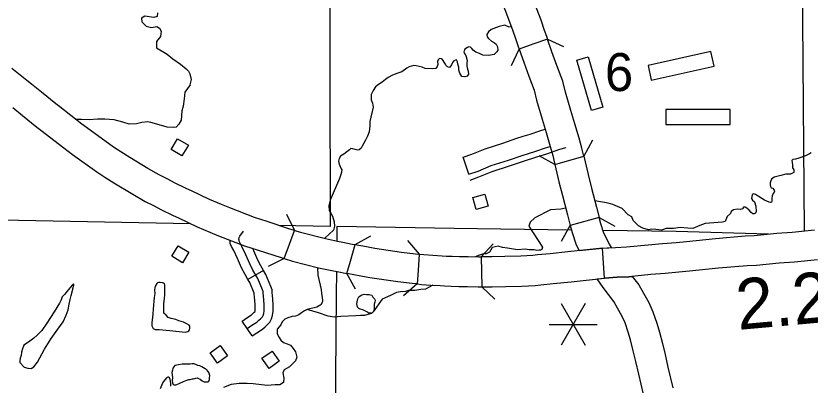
# Model space of a CAD drawing. Extents: x 61396 to 64680, y 55472 to 57605.
# Drawn here: x 62536.1 to 62743.1, y 56330.1 to 56426.3 of the extents above; entities that cross this region are included whole.
import ezdxf

# ---------------------------------------------------------------- set-up
doc = ezdxf.new("R2010")
doc.units = 0
for name, color, linetype in [('15', 7, 'Continuous'), ('32', 7, 'Continuous'), ('35', 7, 'Continuous'), ('37', 7, 'Continuous'), ('4', 7, 'Continuous'), ('45', 7, 'Continuous'), ('48', 7, 'Continuous'), ('5', 7, 'Continuous'), ('56', 7, 'Continuous'), ('57', 7, 'Continuous'), ('6', 7, 'Continuous')]:
    doc.layers.add(name, color=color, linetype=linetype)

msp = doc.modelspace()

# ---------------------------------------------------------------- linework, layer by layer
at = {"layer": '15'}
for p, q in [((62676.6, 56387.58), (62684.11, 56389.78)), ((62688.12, 56373.73), (62680.58, 56371.68))]:
    msp.add_line(p, q, dxfattribs=at)
for points in [[(62668.98, 56435.84), (62669.25, 56435.05), (62670.84, 56430.76), (62672.94, 56425.31), (62673.78, 56422.64), (62674.37, 56421), (62674.64, 56420.26)], [(62661.67, 56433.08), (62661.89, 56432.43), (62663.53, 56428), (62665.56, 56422.73), (62666.38, 56420.14), (62667.02, 56418.37), (62667.27, 56417.66)], [(62674.64, 56420.26), (62670.82, 56418.91), (62667.27, 56417.66), (62668.46, 56414.29), (62669.78, 56410.65), (62671.16, 56406.96), (62671.83, 56404.38), (62673.26, 56399.42), (62674.32, 56395.96), (62675.38, 56392.29), (62676.04, 56389.89), (62676.52, 56387.94), (62676.6, 56387.58)], [(62684.11, 56389.78), (62683.6, 56391.87), (62682.89, 56394.41), (62681.81, 56398.18), (62680.75, 56401.64), (62679.37, 56406.44), (62678.62, 56409.32), (62677.11, 56413.35), (62675.82, 56416.92), (62674.64, 56420.26)], [(62608.67, 56370.42), (62607.53, 56370.76), (62601.62, 56372.71), (62598.29, 56373.8), (62591.81, 56376.25), (62589.69, 56377.15), (62586.56, 56378.46), (62581.82, 56380.7), (62580.47, 56381.34), (62577.46, 56382.82), (62575.72, 56383.78), (62573.41, 56384.91), (62570.48, 56386.55), (62565.79, 56389.39), (62563.47, 56390.89), (62561.55, 56392.13), (62555.47, 56396.5), (62553.28, 56398.14), (62547.49, 56402.6), (62546.5, 56403.41), (62542.75, 56406.41), (62540.14, 56408.54), (62538.95, 56409.48), (62535.04, 56412.59)], [(62535.24, 56402.45), (62537.84, 56400.33), (62541.57, 56397.35), (62542.62, 56396.49), (62548.56, 56391.91), (62550.85, 56390.2), (62557.16, 56385.66), (62559.24, 56384.32), (62561.65, 56382.77), (62566.54, 56379.81), (62569.78, 56377.98), (62572.13, 56376.84), (62573.86, 56375.89), (62577.07, 56374.31), (62578.47, 56373.64), (62583.37, 56371.33), (62586.65, 56369.95), (62588.9, 56369), (62595.7, 56366.42), (62599.19, 56365.29), (62605.19, 56363.3), (62606.02, 56363.06), (62607.38, 56366.84), (62608.67, 56370.42)], [(62684.11, 56389.78), (62684.12, 56389.75), (62685.23, 56384.94), (62686.14, 56381.4), (62687.4, 56376.46), (62688.12, 56373.73)], [(62676.6, 56387.58), (62677.64, 56383.08), (62678.58, 56379.46), (62679.83, 56374.5), (62680.58, 56371.68)], [(62691.35, 56365.93), (62690.83, 56366.78), (62689.36, 56369.68), (62688.55, 56372.12), (62688.12, 56373.73)], [(62680.58, 56371.68), (62681.06, 56369.87), (62682.14, 56366.67), (62682.91, 56365.13)], [(62608.67, 56370.42), (62610.23, 56369.96), (62616.8, 56368.29), (62619.94, 56367.6), (62621.33, 56367.37), (62623.78, 56366.85), (62624.51, 56366.72)], [(62689.5, 56357.98), (62689, 56365.78), (62692.37, 56365.99), (62695.29, 56366.13), (62700.87, 56366.66), (62704.65, 56366.98), (62708.19, 56367.26), (62710.89, 56367.54), (62718.47, 56368.33), (62726.21, 56368.97), (62728.56, 56369.09), (62734.42, 56369.67), (62738.41, 56369.93), (62744.28, 56370.54)], [(62640.69, 56356.44), (62639.4, 56356.56), (62635.62, 56357.02), (62628.36, 56358.03), (62626.03, 56358.49), (62622.35, 56359.17), (62623.26, 56362.38), (62624.51, 56366.72)], [(62624.51, 56366.72), (62627.5, 56366.17), (62629.66, 56365.74), (62636.63, 56364.77), (62640.22, 56364.33), (62641.24, 56364.24), (62640.94, 56359.91), (62640.69, 56356.44)], [(62689.5, 56357.98), (62689, 56365.78), (62679.97, 56364.81), (62675.38, 56364.33), (62672.08, 56364), (62670.8, 56363.86), (62667.7, 56363.72), (62663.55, 56363.6), (62660.16, 56363.52), (62657.99, 56363.52), (62657.33, 56363.53), (62657.43, 56359.6), (62657.53, 56355.71)], [(62682.91, 56365.13), (62689, 56365.78), (62691.35, 56365.93)], [(62606.02, 56363.06), (62608.17, 56362.42), (62615, 56360.68), (62618.45, 56359.93), (62619.87, 56359.69), (62622.35, 56359.17)], [(62641.24, 56364.24), (62642.44, 56364.13), (62644.74, 56363.95), (62647.2, 56363.81), (62648.29, 56363.72), (62649.78, 56363.66), (62651.68, 56363.63), (62653.94, 56363.57), (62656.72, 56363.54), (62657.33, 56363.53)], [(62745.06, 56362.77), (62739.07, 56362.15), (62735.07, 56361.88), (62729.14, 56361.29), (62726.73, 56361.17), (62719.2, 56360.55), (62711.69, 56359.76), (62708.89, 56359.48), (62705.3, 56359.2), (62701.58, 56358.88), (62695.84, 56358.33), (62692.8, 56358.19), (62689.5, 56357.98)], [(62657.53, 56355.71), (62657.89, 56355.7), (62660.26, 56355.7), (62663.76, 56355.79), (62667.99, 56355.91), (62671.41, 56356.07), (62672.89, 56356.23), (62676.17, 56356.56), (62680.79, 56357.04), (62689.5, 56357.98)], [(62687.63, 56357.78), (62689.5, 56357.98), (62692.8, 56358.19), (62695.84, 56358.33), (62696.77, 56358.42)], [(62699.69, 56327.72), (62698.46, 56332.97), (62697.69, 56336.25), (62697.03, 56339), (62696.27, 56341.86), (62695.71, 56343.9), (62694.87, 56346.3), (62694.06, 56348.15), (62692.91, 56350.17), (62691.92, 56351.88), (62689.17, 56355.5), (62687.63, 56357.78)], [(62696.77, 56358.42), (62698.44, 56356.22), (62699.7, 56354.06), (62701.06, 56351.64), (62702.14, 56349.17), (62703.17, 56346.24), (62703.82, 56343.89), (62704.6, 56340.92), (62705.29, 56338.06), (62706.06, 56334.76), (62707.32, 56329.4)], [(62640.69, 56356.44), (62641.79, 56356.34), (62644.21, 56356.16), (62646.66, 56356.01), (62647.84, 56355.92), (62649.58, 56355.85), (62651.52, 56355.82), (62653.8, 56355.76), (62656.59, 56355.73), (62657.53, 56355.71)]]:
    msp.add_lwpolyline(points, dxfattribs=at)
at = {"layer": '32'}
for p, q in [((62600.61, 56359.98), (62596.56, 56357.63)), ((62597.66, 56342.89), (62595.05, 56346.78))]:
    msp.add_line(p, q, dxfattribs=at)
for points in [[(62596.35, 56344.83), (62597.58, 56345.66), (62598.91, 56346.5), (62599.44, 56346.99), (62599.84, 56347.37), (62600.35, 56347.88), (62600.55, 56348.26), (62600.71, 56348.74), (62600.8, 56349.43), (62600.77, 56350.01), (62600.8, 56350.92), (62600.73, 56352.36), (62600.64, 56353.16), (62600.57, 56354.12), (62600.57, 56354.45), (62600.4, 56354.9), (62599.13, 56357.87), (62597.86, 56360.05), (62597.04, 56361.65), (62595.98, 56364.07), (62594.94, 56366.22), (62594.42, 56367.21), (62594.26, 56367.56), (62594.24, 56367.85), (62594.23, 56368.12), (62594.31, 56368.59), (62594.44, 56368.89), (62595.45, 56370.2)], [(62596.56, 56357.63), (62595.81, 56358.92), (62594.93, 56360.64), (62593.85, 56363.09), (62592.85, 56365.17), (62592.31, 56366.18), (62591.96, 56366.97), (62591.9, 56367.71), (62591.9, 56367.86)], [(62600.61, 56359.98), (62599.92, 56361.18), (62599.16, 56362.66), (62598.11, 56365.05), (62597.77, 56365.75)], [(62597.66, 56342.89), (62598.86, 56343.69), (62600.34, 56344.63), (62601.04, 56345.27), (62601.47, 56345.69), (62602.26, 56346.47), (62602.72, 56347.34), (62603, 56348.23), (62603.15, 56349.33), (62603.12, 56350.03), (62603.14, 56350.95), (62603.07, 56352.55), (62602.98, 56353.38), (62602.92, 56354.2), (62602.92, 56354.9), (62602.56, 56355.79), (62601.23, 56358.93), (62600.61, 56359.98)], [(62595.05, 56346.78), (62596.29, 56347.62), (62597.48, 56348.37), (62597.84, 56348.71), (62598.21, 56349.05), (62598.41, 56349.25), (62598.41, 56349.25), (62598.45, 56349.54), (62598.43, 56349.99), (62598.45, 56350.9), (62598.39, 56352.18), (62598.31, 56352.95), (62598.23, 56353.99), (62598.23, 56354), (62597.03, 56356.82), (62596.56, 56357.63)]]:
    msp.add_lwpolyline(points, dxfattribs=at)
at = {"layer": '35'}
for points in [[(62573.02, 56427.09), (62572.87, 56426.19), (62572.02, 56425.89), (62569.68, 56426.29), (62568.84, 56425.69), (62568.89, 56424.75), (62570.08, 56423.65), (62571.47, 56423.31), (62572.82, 56423.55), (62573.51, 56423.11), (62573.96, 56422.36), (62573.76, 56420.92), (62572.77, 56419.67), (62572.77, 56418.03), (62575.54, 56416.32), (62577.01, 56415.11), (62578.97, 56413.76), (62580.48, 56412.49), (62581.09, 56411.88), (62581.46, 56411.2), (62581.81, 56409.74), (62581.45, 56408.38), (62581.51, 56408.32), (62580.1, 56406.42), (62579.9, 56404.69), (62579.64, 56402.83), (62579.34, 56401.59), (62579.28, 56400.3), (62579.13, 56399.14), (62578.54, 56398.12), (62577.84, 56397.34), (62577.06, 56397.19), (62575.49, 56397.3), (62573.4, 56397.92), (62571.29, 56398.54), (62570.37, 56398.67), (62568.88, 56398.5), (62567.54, 56398.2), (62565.63, 56398.14), (62563.95, 56398.65), (62561.68, 56399.24), (62559.27, 56399.38)], [(62665.25, 56423.55), (62664.69, 56423.35), (62663.5, 56423.88), (62662.08, 56423.59), (62659.97, 56422.81), (62659.27, 56422.19), (62658.88, 56421.49), (62658.93, 56420.89), (62659.32, 56420.43), (62660.03, 56419.76), (62660.8, 56419.29), (62661.25, 56418.92), (62661.64, 56418.28), (62661.73, 56417.37), (62661.46, 56416.95), (62660.73, 56416.27), (62659.27, 56416.01), (62657.83, 56416.05), (62656.9, 56416.5), (62655.98, 56416.87), (62655.25, 56417.38), (62654.95, 56417.78), (62654.57, 56418.15), (62654.19, 56418.26), (62653.79, 56418.09), (62653.08, 56417.69), (62652.88, 56416.96), (62653.12, 56416.34), (62653.38, 56415.97), (62653.7, 56414.73), (62653.66, 56413.88), (62653.59, 56413.19), (62653.77, 56412.44), (62653.94, 56411.91), (62654.03, 56411.1), (62653.7, 56410.62), (62653.08, 56410.41), (62652.36, 56410.54), (62651.83, 56411.37), (62651.58, 56412.21), (62651.53, 56412.93), (62651.32, 56413.74), (62651.17, 56414.37), (62651.04, 56414.71), (62650.94, 56414.83), (62650.69, 56414.79), (62650.23, 56414.62), (62649.9, 56414.17), (62649.63, 56413.6), (62649.24, 56412.99), (62648.93, 56412.91), (62648.33, 56413.21), (62648.06, 56413.7)], [(62648.06, 56413.7), (62647.76, 56414.29), (62647.5, 56414.72), (62647.24, 56415.06), (62647.05, 56415.15), (62646.48, 56415.25), (62646.15, 56414.83), (62645.97, 56414.42), (62646.03, 56413.64), (62645.89, 56413.13), (62645.53, 56412.65), (62644.75, 56412.5), (62642.8, 56412.59), (62641.98, 56412.97), (62640.4, 56413.3), (62639.8, 56413.38), (62638.56, 56413.02), (62638.01, 56412.66), (62636.69, 56411.74), (62635.36, 56411.29), (62634.21, 56410.84), (62633.1, 56410.28), (62632.43, 56409.72), (62631.54, 56409.03), (62630.59, 56408.41), (62629.83, 56407.82), (62629.2, 56406.89), (62628.73, 56405.8), (62628.71, 56404.45), (62629.05, 56403.59), (62629.2, 56402.52), (62628.32, 56398.76), (62628.38, 56397.67), (62628.18, 56396.12), (62627.74, 56394.98), (62627.21, 56393.89), (62626.77, 56393.16), (62626.32, 56392.33), (62626.09, 56391.85), (62625.53, 56391.42), (62625.19, 56391.35), (62624.53, 56391.45), (62623.93, 56391.69), (62623.4, 56391.73), (62623, 56391.44), (62622.39, 56390.92), (62621.56, 56390.29), (62620.73, 56389.76), (62620.34, 56389.19), (62620.18, 56388.43), (62620.39, 56387.68), (62620.83, 56386.47), (62621.03, 56386.16), (62620.9, 56385.28), (62620.47, 56383.92), (62618.04, 56378.25), (62617.62, 56376.89), (62617.72, 56375.61), (62618.25, 56374.75), (62618.61, 56374.1), (62619.06, 56372.67), (62619.1, 56371.51), (62618.88, 56370.5), (62616.57, 56368.35)], [(62559.27, 56399.38), (62557.38, 56399.42), (62555.14, 56399.22), (62553.19, 56399.31), (62551.83, 56399.33)], [(62743.43, 56390.66), (62742.92, 56390.33), (62741.9, 56389.85), (62740.21, 56389.2), (62739.28, 56389.01), (62738.64, 56388.92), (62738.31, 56388.6), (62738.4, 56388.13), (62738.54, 56387.53), (62738.52, 56386.68), (62738.87, 56386.17), (62738.91, 56385.82), (62738.87, 56385.52), (62738.54, 56385.29), (62737.99, 56385.08), (62736.81, 56385.03), (62735.46, 56384.71), (62733.72, 56384.29), (62733.08, 56383.8), (62732.89, 56383.36), (62732.73, 56382.81), (62732.68, 56382.25), (62732.75, 56381.86), (62732.94, 56381.53), (62733.38, 56381.4), (62733.72, 56380.93), (62733.82, 56380.65), (62733.75, 56380.35), (62733.52, 56380.01), (62733.26, 56379.4), (62733.15, 56378.76), (62733.15, 56378.22), (62733.15, 56377.94), (62733.03, 56377.74), (62732.75, 56377.64), (62732.45, 56377.76), (62731.25, 56378.27), (62728.84, 56379.8), (62728.37, 56379.96), (62728, 56379.73), (62727.89, 56379.15), (62727.86, 56378.71), (62728.12, 56378.32), (62728.61, 56377.81), (62728.95, 56376.76), (62729.05, 56375.33), (62728.86, 56374.91), (62728.56, 56374.73), (62728.17, 56374.7), (62727.73, 56375.03), (62727.19, 56375.65), (62726.59, 56376.21), (62726.15, 56376.46), (62725.76, 56376.42), (62725.46, 56376.07), (62724.9, 56375.81), (62724.12, 56375.95), (62723.17, 56375.79), (62722.53, 56375.36), (62722.34, 56374.83), (62721.52, 56374.01)], [(62721.52, 56374.01), (62720.93, 56372.72), (62720.31, 56372.54), (62719.13, 56372.47), (62715.76, 56372.23), (62714.35, 56371.71), (62712.56, 56370.93), (62711.22, 56370.98), (62709.24, 56371.19), (62707.51, 56370.88), (62705.58, 56370.88), (62704.4, 56370.46), (62702.86, 56370.62), (62701.84, 56370.74), (62700.96, 56370.59), (62699.53, 56370.98), (62698.34, 56371.62), (62696.99, 56372.97), (62696.6, 56373.98), (62695.67, 56374.48), (62694.11, 56376.1), (62691.69, 56377.16), (62690.44, 56377.47), (62687.02, 56378.15)], [(62679.39, 56376.23), (62678.17, 56375.97), (62675.45, 56375.79), (62671.34, 56373.67), (62670.1, 56372.55), (62669.79, 56371.5), (62673.32, 56366.04), (62673.21, 56365.45), (62672.8, 56365.26), (62672.47, 56365.23), (62671.87, 56365.19), (62671.17, 56365.37), (62669.91, 56365.37), (62668.87, 56365.48), (62666.8, 56365.32), (62664.24, 56365.77), (62662.96, 56365.99), (62661.76, 56366.29), (62660.25, 56365.99), (62659.5, 56364.71), (62658.71, 56364.33), (62657.98, 56364.29), (62657.43, 56364.12), (62656.67, 56363.84), (62656.08, 56363.64), (62655.88, 56363.55)], [(62614.71, 56360.76), (62614.7, 56360.7), (62614.75, 56358.71), (62615.69, 56354.96), (62615.72, 56353.92), (62615.9, 56353.02), (62616.03, 56352.05), (62615.95, 56351.61), (62615.53, 56351.03), (62614.51, 56350.37), (62611.99, 56349.75), (62611.32, 56349.42), (62610.49, 56348.92), (62609.81, 56348.37), (62608.95, 56348.02), (62608.07, 56347.97), (62606.95, 56347.62), (62606.15, 56347.28), (62605.48, 56346.58), (62605.13, 56345.81), (62604.22, 56344.7), (62604.15, 56343.44), (62604.71, 56342.46), (62605.13, 56341.83), (62605.82, 56341.2), (62606.8, 56340.85), (62607.64, 56340.51), (62608.34, 56339.6), (62608.97, 56338.76), (62609.32, 56337.36)], [(62574.67, 56356.62), (62574.58, 56356.66), (62574.28, 56356.76), (62573.71, 56356.8), (62573.31, 56356.8), (62572.95, 56356.76), (62572.79, 56356.56), (62572.55, 56356.12), (62572.31, 56355.52), (62572.23, 56354.84), (62572.27, 56353.96), (62572.15, 56352.87), (62572.07, 56351.99), (62571.91, 56350.95), (62571.87, 56349.86), (62571.75, 56348.66), (62571.67, 56347.74), (62571.55, 56346.42), (62571.55, 56345.57), (62571.83, 56344.81), (62572.39, 56344.61), (62573.39, 56344.57), (62576.24, 56344.29), (62580.21, 56343.85), (62580.86, 56344.01), (62581.14, 56344.25), (62581.34, 56344.49), (62581.46, 56344.81), (62581.46, 56345.01), (62581.42, 56345.45), (62581.26, 56345.73), (62580.66, 56346.05), (62579.77, 56346.46), (62578.53, 56346.86), (62577.73, 56347.22), (62576.56, 56347.46), (62575.8, 56347.7), (62575.24, 56348.34), (62574.64, 56348.82), (62574.64, 56349.26), (62574.64, 56350.11), (62574.68, 56351.39), (62574.8, 56352.67), (62574.88, 56353.68), (62574.87, 56355.26), (62574.88, 56355.75), (62574.87, 56356.03), (62574.87, 56356.18), (62574.85, 56356.37), (62574.81, 56356.49), (62574.67, 56356.62)], [(62644.8, 56356.12), (62642.86, 56355.12), (62641.63, 56354.97), (62640.05, 56354.78), (62638.4, 56354.7), (62637.6, 56354.51), (62636.37, 56354.39), (62635.3, 56354.18), (62633.71, 56353.47), (62631.54, 56352.49), (62629.23, 56349.21), (62628.78, 56348.73), (62627.82, 56348.52), (62626.92, 56348.18), (62625.92, 56348.18), (62624.67, 56348.14), (62620.81, 56347.94), (62619.03, 56347.8), (62617.48, 56348.04), (62614.99, 56348.91), (62611.99, 56349.75)], [(62625.5, 56353.11), (62626.05, 56353.56), (62626.83, 56353.8), (62627.47, 56353.73), (62628.13, 56353.73), (62628.89, 56353.49), (62629.16, 56352.97), (62629.58, 56352.56), (62629.75, 56352.25), (62629.61, 56351.73), (62629.47, 56351.21), (62629.44, 56350.18), (62629.4, 56349.32), (62628.95, 56348.94), (62628.51, 56348.8), (62628.09, 56348.83), (62627.57, 56349.18), (62627.23, 56349.38), (62626.5, 56349.73), (62625.85, 56349.83), (62625.47, 56350.01), (62625.12, 56350.39), (62625.02, 56350.8), (62624.92, 56351.25), (62625.12, 56352.18), (62625.23, 56352.56), (62625.5, 56353.11)], [(62609.32, 56337.36), (62608.97, 56336.38), (62607.43, 56334.85), (62606.03, 56334.08), (62605.68, 56333.24), (62605.96, 56331.91), (62605.82, 56330.73), (62604.92, 56330.17), (62603.67, 56330.16), (62601.57, 56329.99), (62597.9, 56330.38), (62596.33, 56330.52), (62594.32, 56330.49), (62592.2, 56330.2), (62590.22, 56329.48)], [(62576.5, 56329.83), (62576.47, 56330.53), (62576.38, 56331.13), (62576.26, 56331.53), (62576.08, 56331.98), (62575.9, 56332.13), (62575.69, 56332.16), (62575.32, 56332.01), (62574.57, 56331.01), (62574.18, 56330.41), (62573.69, 56329.11)]]:
    msp.add_lwpolyline(points, dxfattribs=at)
for points in [[(62550.73, 56356.13), (62549.48, 56354.6), (62548.75, 56353.69), (62548.18, 56353.13), (62547.84, 56352.28), (62547.44, 56351.43), (62546.08, 56349.16), (62544.16, 56346.22), (62542.8, 56344.35), (62541.61, 56343.1), (62540.76, 56342.31), (62539.34, 56341.23), (62538.15, 56340.49), (62537.81, 56339.53), (62537.58, 56338.62), (62537.47, 56337.77), (62537.19, 56337.1), (62537.07, 56336.36), (62537.07, 56335.96), (62538.26, 56334.72), (62539.23, 56334.49), (62540.08, 56334.38), (62540.76, 56334.83), (62541.72, 56336.08), (62543.53, 56339.42), (62545.29, 56342.19), (62547.05, 56344.69), (62548.41, 56346.61), (62549.2, 56348.31), (62549.71, 56349.73), (62549.99, 56351.14), (62550.22, 56352.39), (62550.5, 56353.47), (62551, 56355.43), (62551.12, 56355.83), (62551.16, 56356.12), (62551.16, 56356.3), (62551.08, 56356.36), (62550.94, 56356.34)], [(62583.69, 56331.83), (62584.14, 56331.6), (62584.6, 56331.22), (62585.13, 56330.97), (62585.59, 56330.89), (62585.94, 56330.89), (62586.22, 56330.97), (62586.37, 56331.12), (62586.52, 56331.53), (62586.58, 56331.91), (62586.6, 56332.54), (62586.47, 56333.17), (62586.2, 56333.6), (62585.76, 56334.14), (62585.46, 56334.34), (62584.98, 56334.59), (62584.52, 56334.82), (62584.07, 56335.07), (62583.51, 56335.2), (62582.95, 56335.45), (62582.42, 56335.58), (62582.04, 56335.58), (62581.48, 56335.5), (62580.8, 56335.5), (62580.37, 56335.5), (62579.38, 56335.5), (62578.44, 56335.38), (62578.01, 56335.28), (62577.48, 56335.15), (62577.25, 56334.85), (62577.02, 56334.47), (62576.87, 56333.98), (62576.74, 56333.38), (62576.89, 56332.08), (62576.84, 56331.27), (62576.92, 56330.69), (62577.1, 56330.26), (62577.32, 56330.18), (62577.78, 56330.11), (62578.03, 56330.26), (62578.77, 56330.56), (62579.78, 56331.02), (62580.62, 56331.35), (62581.18, 56331.53), (62581.53, 56331.58), (62582.11, 56331.68), (62582.34, 56331.73), (62583, 56331.88), (62583.31, 56331.93)]]:
    msp.add_lwpolyline(points, close=True, dxfattribs=at)
at = {"layer": '37'}
for points in [[(62674.64, 56420.26), (62678.86, 56418.31)], [(62665.28, 56413.42), (62667.27, 56417.66)], [(62686.36, 56393.9), (62684.11, 56389.78)], [(62676.6, 56387.58), (62672.5, 56389.82)], [(62606.63, 56374.64), (62608.67, 56370.42)], [(62688.12, 56373.73), (62692.19, 56371.47)], [(62678.28, 56367.59), (62680.58, 56371.68)], [(62624.51, 56366.72), (62628.61, 56368.99)], [(62638.16, 56367.77), (62641.24, 56364.24)], [(62657.33, 56363.53), (62660.5, 56366.94)], [(62606.02, 56363.06), (62601.87, 56361.01)], [(62624.61, 56355.11), (62622.35, 56359.17)], [(62640.69, 56356.44), (62637.16, 56353.37)], [(62660.95, 56352.5), (62657.53, 56355.71)]]:
    msp.add_lwpolyline(points, dxfattribs=at)
at = {"layer": '4'}
for points in [[(62581.63, 56372.15), (62451.61, 56374.62), (62451.37, 56374.62), (62288.25, 56378.62), (62286.91, 56378.65), (62230.77, 56379.8)], [(62617.99, 56371.46), (62604.64, 56371.71)]]:
    msp.add_lwpolyline(points, dxfattribs=at)
at = {"layer": '45'}
msp.add_line((62654.19, 56385.03), (62652.67, 56389.46), dxfattribs=at)
for points in [[(62668.3, 56394.93), (62670.17, 56395.51), (62672.67, 56396.33), (62674.06, 56396.81)], [(62652.67, 56389.46), (62654.93, 56390.24), (62658.37, 56391.68), (62663, 56393.18), (62666.64, 56394.42), (62668.3, 56394.93)], [(62654.47, 56383.54), (62656.8, 56384.34), (62660.23, 56385.78), (62664.77, 56387.25), (62668.4, 56388.49), (62671.91, 56389.56), (62674.46, 56390.4), (62677.86, 56391.57), (62679.51, 56391.99)], [(62669.68, 56390.45), (62671.58, 56391.04), (62674.17, 56391.89), (62675.37, 56392.3)], [(62654.19, 56385.03), (62656.6, 56385.85), (62660.01, 56387.29), (62664.47, 56388.73), (62668.09, 56389.96), (62669.68, 56390.45)]]:
    msp.add_lwpolyline(points, dxfattribs=at)
at = {"layer": '48'}
for p, q in [((62684.5, 56351.32), (62678.25, 56340.5)), ((62678.25, 56351.32), (62684.5, 56340.5)), ((62675.13, 56345.91), (62687.63, 56345.91))]:
    msp.add_line(p, q, dxfattribs=at)
at = {"layer": '5'}
msp.add_lwpolyline([(62617.74, 56493.19), (62618, 56371.46)], dxfattribs=at)
at = {"layer": '56'}
for points in [[(62682.3, 56414.8), (62685.3, 56415.67), (62689.11, 56402.54), (62686.11, 56401.67)], [(62576.56, 56391.5), (62578.23, 56394.29), (62581.03, 56392.61), (62579.35, 56389.82)], [(62656.08, 56375.82), (62655.16, 56378.94), (62658.28, 56379.86), (62659.21, 56376.75)], [(62576.69, 56363.65), (62578.39, 56366.42), (62581.17, 56364.71), (62579.47, 56361.94)], [(62586.68, 56338.47), (62589.31, 56340.38), (62591.23, 56337.74), (62588.6, 56335.83)], [(62602.07, 56334.43), (62600.2, 56337.09), (62602.88, 56338.96), (62604.74, 56336.3)]]:
    msp.add_lwpolyline(points, close=True, dxfattribs=at)
at = {"layer": '57'}
for p, q in [((62717.26, 56417.02), (62700.86, 56413.38)), ((62718.11, 56413.21), (62717.26, 56417.02)), ((62700.86, 56413.38), (62701.71, 56409.56)), ((62701.71, 56409.56), (62718.11, 56413.21)), ((62722.28, 56401.96), (62705.49, 56401.96)), ((62705.49, 56401.96), (62705.49, 56398.05)), ((62722.28, 56398.05), (62722.28, 56401.96)), ((62705.49, 56398.05), (62722.28, 56398.05))]:
    msp.add_line(p, q, dxfattribs=at)
at = {"layer": '6'}
for points in [[(62740.25, 56534.94), (62741.53, 56370.26)], [(62680.85, 56370.49), (62650.35, 56370.91), (62619.77, 56371.43), (62619.74, 56367.64)], [(62732.29, 56369.46), (62708.2, 56370.11), (62689.01, 56370.38)], [(62619.66, 56359.73), (62619.6, 56353.58), (62619.11, 56300.4), (62618.97, 56285.69)]]:
    msp.add_lwpolyline(points, dxfattribs=at)

# ---------------------------------------------------------------- texts
at = {"layer": '48'}
msp.add_text('2.2', height=13.2, rotation=5.1513, dxfattribs=at).set_placement((62724.37, 56344.45))
at = {"layer": '56'}
msp.add_text('6', height=9.9, dxfattribs=at).set_placement((62689.63, 56406.73))

doc.saveas('drawing.dxf')
